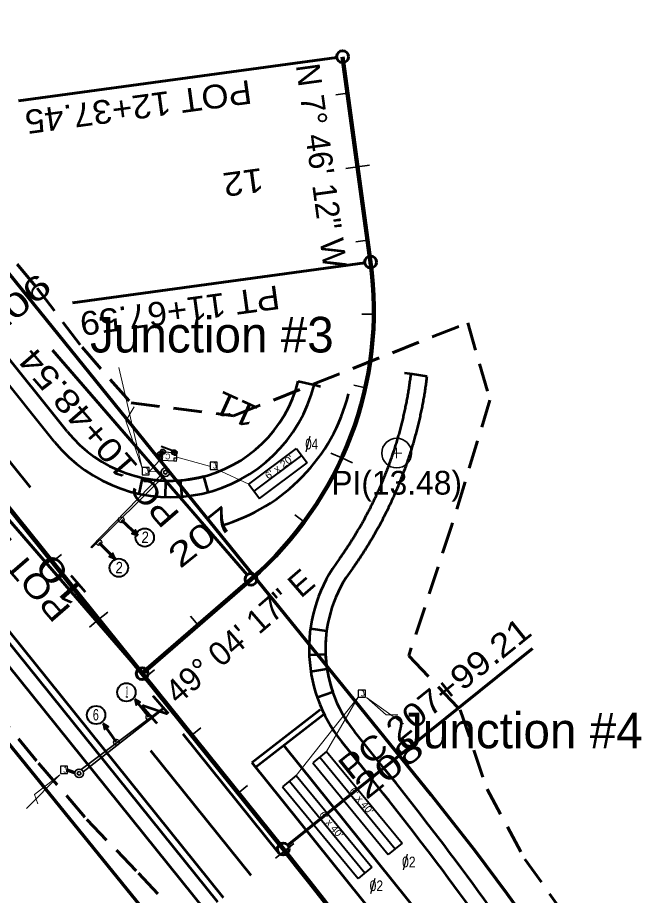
# Model space of a CAD drawing. Extents: x 2717836 to 2719883, y 337327 to 339813.
# Drawn here: x 2718311.5 to 2718519.7, y 339092.2 to 339388.1 of the extents above; entities that cross this region are included whole.
import ezdxf
from ezdxf.enums import TextEntityAlignment as Align

# ---------------------------------------------------------------- set-up
doc = ezdxf.new("R2010")
doc.units = 0
doc.header["$LTSCALE"] = 3.2
doc.header["$PDMODE"] = 32
doc.header["$PDSIZE"] = 1.6
doc.linetypes.add('MEDIUM_DASHED', pattern=[4.5, 3, -1.5])
doc.linetypes.add('SHORT_DASHED', pattern=[2.7, 1.5, -1.2])
for name, color, linetype, lineweight in [('1', 7, 'Continuous', 106), ('17', 7, 'Continuous', 40), ('18', 7, 'Continuous', 35), ('2', 7, 'Continuous', 13), ('22', 7, 'SHORT_DASHED', 60), ('23', 7, 'Continuous', 70), ('28', 7, 'Continuous', 25), ('31', 7, 'Continuous', 35), ('4', 7, 'Continuous', 53), ('50', 7, 'Continuous', 13), ('55', 7, 'Continuous', 13), ('7', 7, 'Continuous', 53)]:
    doc.layers.add(name, color=color, linetype=linetype, lineweight=lineweight)

msp = doc.modelspace()

# ---------------------------------------------------------------- linework, layer by layer
at = {"layer": '1'}
for p, q in [((2717900.042, 339730.601), (2718401.027, 339107.905)), ((2718430.449, 339305.67), (2718421.004, 339374.89)), ((2718353.494, 339166.985), (2718390.165, 339198.783))]:
    msp.add_line(p, q, dxfattribs=at)
for centre, radius, start, end in [((2718311.551, 339289.446), 120, 310.92863, 7.77011), ((2717543.972, 338418.37), 1100, 26.79977, 38.81809)]:
    msp.add_arc(centre, radius, start, end, dxfattribs=at)
at = {"layer": '17'}
for p, q in [((2718365.285, 339241.467), (2718359.882, 339243.563)), ((2718389.458, 339230.856), (2718405.455, 339242.861)), ((2718391.259, 339228.457), (2718407.255, 339240.461)), ((2718405.455, 339242.861), (2718409.056, 339238.061)), ((2718393.059, 339226.057), (2718409.056, 339238.061)), ((2718389.458, 339230.856), (2718393.059, 339226.057)), ((2718415.627, 339140.709), (2718410.994, 339136.896)), ((2718415.627, 339140.709), (2718441.047, 339109.825)), ((2718410.994, 339136.896), (2718436.414, 339106.012)), ((2718413.311, 339138.803), (2718438.731, 339107.919)), ((2718405.421, 339132.685), (2718400.788, 339128.872)), ((2718403.105, 339130.779), (2718428.525, 339099.895)), ((2718405.421, 339132.685), (2718430.841, 339101.801)), ((2718400.788, 339128.872), (2718426.208, 339097.988)), ((2718441.047, 339109.825), (2718436.414, 339106.012)), ((2718430.841, 339101.801), (2718426.208, 339097.988))]:
    msp.add_line(p, q, dxfattribs=at)
at = {"layer": '17', "lineweight": 25}
for p, q in [((2718359.423, 339239.906), (2718359.482, 339240.862)), ((2718360.493, 339241.749), (2718364.327, 339241.523)), ((2718365.17, 339239.551), (2718365.229, 339240.507)), ((2718360.324, 339238.874), (2718364.158, 339238.648))]:
    msp.add_line(p, q, dxfattribs=at)
for points in [[(2718359.478, 339240.846), (2718360.436, 339240.789), (2718360.493, 339241.749), (2718359.534, 339241.805)], [(2718364.271, 339240.564), (2718365.229, 339240.507), (2718365.285, 339241.467), (2718364.327, 339241.523)], [(2718359.365, 339238.93), (2718360.324, 339238.874), (2718360.38, 339239.833), (2718359.422, 339239.889)], [(2718364.155, 339238.648), (2718365.113, 339238.592), (2718365.17, 339239.551), (2718364.211, 339239.607)], [(2718376.391, 339238.235), (2718376.391, 339235.835), (2718378.791, 339235.835), (2718378.791, 339238.235)], [(2718353.506, 339236.405), (2718353.506, 339234.005), (2718355.906, 339234.005), (2718355.906, 339236.405)], [(2718426.282, 339161.454), (2718426.282, 339159.054), (2718428.682, 339159.054), (2718428.682, 339161.454)], [(2718325.972, 339135.761), (2718325.972, 339133.361), (2718328.372, 339133.361), (2718328.372, 339135.761)]]:
    msp.add_lwpolyline(points, close=True, dxfattribs=at)
at = {"layer": '17'}
for p in [(2718359.42, 339239.889), (2718359.478, 339240.846), (2718360.493, 339241.749), (2718364.327, 339241.523)]:
    msp.add_point(p, dxfattribs=at)
at = {"layer": '18'}
for p, q in [((2718336.568, 339209.363), (2718360.775, 339233.522)), ((2718358.969, 339231.639), (2718358.936, 339231.635)), ((2718360.321, 339155.209), (2718332.995, 339134.645)), ((2718335.045, 339136.259), (2718335.078, 339136.258))]:
    msp.add_line(p, q, dxfattribs=at)
at = {"layer": '18', "lineweight": 60}
for p, q in [((2718352.077, 339213.49), (2718346.526, 339218.755)), ((2718344.395, 339205.645), (2718339.02, 339211.091)), ((2718350.989, 339158.435), (2718355.688, 339152.397)), ((2718340.326, 339150.222), (2718344.739, 339143.973))]:
    msp.add_line(p, q, dxfattribs=at)
at = {"layer": '18'}
for points in [[(2718360.099, 339234.174), (2718336.331, 339209.685), (2718336.568, 339209.363)], [(2718333.574, 339133.905), (2718360.512, 339154.857), (2718360.321, 339155.209)]]:
    msp.add_lwpolyline(points, dxfattribs=at)
at = {"layer": '18', "lineweight": 40}
for points in [[(2718352.077, 339213.49), (2718351.247, 339215.459), (2718350.068, 339214.215)], [(2718344.395, 339205.645), (2718343.63, 339207.64), (2718342.41, 339206.436)], [(2718350.989, 339158.435), (2718351.514, 339156.364), (2718352.867, 339157.417)], [(2718340.326, 339150.222), (2718340.755, 339148.13), (2718342.155, 339149.118)]]:
    msp.add_lwpolyline(points, close=True, dxfattribs=at)
at = {"layer": '18'}
for centre, radius in [((2718361.329, 339234.86), 1.448), ((2718361.329, 339234.86), 0.621), ((2718332.26, 339133.396), 1.448), ((2718332.26, 339133.396), 0.621)]:
    msp.add_circle(centre, radius, dxfattribs=at)
at = {"layer": '18', "lineweight": 25}
for centre in [(2718346.453, 339218.821), (2718338.949, 339211.159), (2718355.75, 339152.321), (2718344.799, 339143.894)]:
    msp.add_circle(centre, 0.96, dxfattribs=at)
at = {"layer": '18', "lineweight": 40}
for centre in [(2718354.383, 339212.863), (2718345.636, 339202.653), (2718348.187, 339160.716), (2718337.983, 339153.058)]:
    msp.add_circle(centre, 3.09, dxfattribs=at)
at = {"layer": '2', "lineweight": 53}
for p, q in [((2718390.451, 339137.002), (2718413.427, 339154.882)), ((2718391.68, 339135.423), (2718414.655, 339153.303)), ((2718328.377, 339134.473), (2718330.81, 339133.637))]:
    msp.add_line(p, q, dxfattribs=at)
at = {"layer": '2', "linetype": 'MEDIUM_DASHED', "lineweight": 53}
for p, q in [((2718328.352, 339134.694), (2718330.859, 339133.809)), ((2718328.377, 339134.325), (2718330.884, 339133.464))]:
    msp.add_line(p, q, dxfattribs=at)
at = {"layer": '2'}
for points in [[(2718345.69, 339270.157), (2718353.486, 339236.226), (2718348.029, 339252.217), (2718350.758, 339256.897)], [(2718441.582, 339150.035), (2718429.108, 339159.005), (2718435.735, 339153.155), (2718439.633, 339153.155)], [(2718314.506, 339121.564), (2718325.81, 339132.874), (2718317.235, 339126.244), (2718318.404, 339123.124)]]:
    msp.add_lwpolyline(points, dxfattribs=at)
at = {"layer": '22', "linetype": 'MEDIUM_DASHED'}
for p, q in [((2718302.106, 339316.085), (2718318.127, 339296.888)), ((2718384.304, 339253.87), (2718463.152, 339285.219)), ((2718463.152, 339285.219), (2718470.67, 339259.182)), ((2718349.808, 339258.203), (2718384.304, 339253.87)), ((2718470.67, 339259.182), (2718457.714, 339216.671)), ((2718457.714, 339216.671), (2718443.286, 339172.977)), ((2718443.286, 339172.977), (2718460.664, 339154.801)), ((2718302.767, 339156.183), (2718318.581, 339136.82)), ((2718460.664, 339154.801), (2718469.661, 339128.028)), ((2718318.581, 339136.82), (2718334.858, 339117.828)), ((2718469.661, 339128.028), (2718482.392, 339104.5)), ((2718334.858, 339117.828), (2718352.29, 339099.766)), ((2718352.29, 339099.766), (2718369.341, 339081.436))]:
    msp.add_line(p, q, dxfattribs=at)
for points in [[(2718318.127, 339296.888), (2718333.232, 339276.954), (2718349.808, 339258.203)], [(2718482.392, 339104.5), (2718497.743, 339082.997), (2718512.6, 339061.15)]]:
    msp.add_lwpolyline(points, dxfattribs=at)
at = {"layer": '23'}
for points in [[(2718450.804, 339126.177), (2718423.202, 339160.278), (2718356.64, 339242.515), (2718281.562, 339335.271)], [(2718625.836, 338603.023), (2718449.262, 338959.135), (2718424.429, 339000.578), (2718281.942, 339176.113)]]:
    msp.add_lwpolyline(points, dxfattribs=at)
msp.add_arc((2717727.191, 338544.436), 928.46, 26.92138, 38.79718, dxfattribs=at)
at = {"layer": '28'}
for p, q in [((2718408.758, 339241.752), (2718410.146, 339246.981)), ((2718441.491, 339100.911), (2718442.87, 339106.142)), ((2718430.557, 339092.888), (2718431.936, 339098.119))]:
    msp.add_line(p, q, dxfattribs=at)
at = {"layer": '31', "lineweight": 60}
for p, q in [((2718419.022, 339374.62), (2718311.858, 339359.997)), ((2718428.468, 339305.399), (2718329.979, 339291.96)), ((2718388.855, 339200.294), (2718323.24, 339275.965)), ((2718352.184, 339168.496), (2718281.617, 339249.878)), ((2718402.585, 339109.158), (2718484.989, 339175.456))]:
    msp.add_line(p, q, dxfattribs=at)
at = {"layer": '31'}
for p, q in [((2718422.687, 339362.557), (2718418.724, 339362.016)), ((2718426.067, 339337.786), (2718422.104, 339337.245)), ((2718426.067, 339337.786), (2718430.03, 339338.327)), ((2718429.447, 339313.016), (2718425.484, 339312.475)), ((2718431.544, 339288.134), (2718427.544, 339288.177)), ((2718428.678, 339263.344), (2718424.774, 339264.214)), ((2718420.747, 339239.683), (2718417.107, 339241.342)), ((2718420.747, 339239.683), (2718424.386, 339238.024)), ((2718408.093, 339218.174), (2718404.875, 339220.55)), ((2718323.166, 339204.681), (2718326.282, 339207.189)), ((2718391.264, 339199.748), (2718388.607, 339202.738)), ((2718338.837, 339185.203), (2718341.953, 339187.71)), ((2718338.837, 339185.203), (2718335.72, 339182.696)), ((2718372.382, 339183.363), (2718369.762, 339186.385)), ((2718353.494, 339166.985), (2718350.874, 339170.007)), ((2718353.494, 339166.985), (2718356.114, 339163.963)), ((2718354.508, 339165.724), (2718357.625, 339168.232)), ((2718370.179, 339146.246), (2718373.296, 339148.753)), ((2718385.851, 339126.767), (2718388.967, 339129.275)), ((2718401.522, 339107.289), (2718398.403, 339104.784)), ((2718401.522, 339107.289), (2718404.64, 339109.794))]:
    msp.add_line(p, q, dxfattribs=at)
at = {"layer": '31', "lineweight": 60}
for centre in [(2718421.004, 339374.89), (2718430.449, 339305.67), (2718390.165, 339198.783), (2718353.494, 339166.985), (2718401.027, 339107.905)]:
    msp.add_circle(centre, 2, dxfattribs=at)
at = {"layer": '31'}
msp.add_circle((2718439.229, 339241.326), 5, dxfattribs=at)
at = {"layer": '4'}
for p, q in [((2718323.984, 339245.141), (2718233.831, 339357.196)), ((2718221.365, 339347.167), (2718315.812, 339229.774)), ((2718193.316, 339324.6), (2718380.769, 339091.606)), ((2718444.565, 339267.916), (2718441.886, 339268.255)), ((2718413.545, 339263.674), (2718410.941, 339264.386)), ((2718367.252, 339146.694), (2718399.468, 339106.651)), ((2718401.177, 339142.814), (2718473.847, 339052.489)), ((2718430.634, 339131.725), (2718420.755, 339144.004)), ((2718356.351, 339141.1), (2718390.119, 339099.129)), ((2718390.451, 339137.002), (2718461.947, 339048.136))]:
    msp.add_line(p, q, dxfattribs=at)
for centre, radius, start, end in [((2718362.941, 339276.483), 50, 218.81809, 345.8429), ((2718362.941, 339276.483), 62, 286.08123, 345.8429), ((2718459.709, 339175.349), 50, 142.40011, 218.81809), ((2717543.972, 338418.37), 1138, 33.56822, 38.81809)]:
    msp.add_arc(centre, radius, start, end, dxfattribs=at)
msp.add_spline([(2718420.093, 339205.853), (2718420.618, 339206.601), (2718421.145, 339207.362), (2718421.66, 339208.116), (2718422.176, 339208.883), (2718422.68, 339209.644), (2718423.18, 339210.408), (2718423.68, 339211.185), (2718424.169, 339211.955), (2718424.652, 339212.729), (2718425.136, 339213.515), (2718425.609, 339214.294), (2718426.082, 339215.086), (2718426.544, 339215.871), (2718427, 339216.659), (2718427.458, 339217.46), (2718427.903, 339218.254), (2718428.343, 339219.05), (2718428.784, 339219.859), (2718429.213, 339220.661), (2718429.642, 339221.475), (2718430.06, 339222.282), (2718430.473, 339223.092), (2718430.886, 339223.914), (2718431.287, 339224.729), (2718431.683, 339225.546), (2718432.079, 339226.376), (2718432.463, 339227.198), (2718432.847, 339228.032), (2718433.221, 339228.859), (2718433.589, 339229.687), (2718433.956, 339230.529), (2718434.312, 339231.362), (2718434.663, 339232.197), (2718435.013, 339233.045), (2718435.352, 339233.885), (2718435.69, 339234.737), (2718436.018, 339235.58), (2718436.34, 339236.426), (2718436.661, 339237.284), (2718436.971, 339238.133), (2718437.28, 339238.994), (2718437.579, 339239.847), (2718437.872, 339240.702), (2718438.163, 339241.569), (2718438.445, 339242.427), (2718438.72, 339243.287), (2718438.994, 339244.159), (2718439.258, 339245.022), (2718439.52, 339245.897), (2718439.772, 339246.762), (2718440.018, 339247.63), (2718440.262, 339248.509), (2718440.496, 339249.379), (2718440.725, 339250.25), (2718440.951, 339251.134), (2718441.168, 339252.008), (2718441.382, 339252.894), (2718441.587, 339253.77), (2718441.786, 339254.647), (2718441.981, 339255.536), (2718442.169, 339256.416), (2718442.35, 339257.296), (2718442.527, 339258.188), (2718442.697, 339259.071), (2718442.862, 339259.965), (2718443.02, 339260.849), (2718443.171, 339261.733), (2718443.319, 339262.63), (2718443.458, 339263.516), (2718443.591, 339264.403), (2718443.721, 339265.302), (2718443.842, 339266.19), (2718444.069, 339267.978)], degree=3, dxfattribs=at)
at = {"layer": '50'}
for p, q in [((2718356.003, 339235.25), (2718359.444, 339238.904)), ((2718365.203, 339239.888), (2718376.229, 339236.937)), ((2718355.933, 339235.11), (2718359.866, 339234.969)), ((2718378.791, 339235.835), (2718389.458, 339230.856)), ((2718426.282, 339159.054), (2718405.421, 339132.685)), ((2718426.282, 339159.054), (2718415.627, 339140.709))]:
    msp.add_line(p, q, dxfattribs=at)
at = {"layer": '55'}
for p, q in [((2718439.229, 339243.076), (2718439.229, 339239.576)), ((2718440.979, 339241.326), (2718437.479, 339241.326))]:
    msp.add_line(p, q, dxfattribs=at)
at = {"layer": '7'}
for p, q in [((2718328.27, 339248.589), (2718238.01, 339360.777)), ((2718191.368, 339323.033), (2718378.821, 339090.039)), ((2718187.473, 339319.899), (2718374.925, 339086.905)), ((2718449.498, 339267.099), (2718444.565, 339267.916)), ((2718406.09, 339265.6), (2718410.941, 339264.386)), ((2718352.475, 339227.476), (2718353.569, 339232.867)), ((2718361.317, 339226.49), (2718361.437, 339231.966)), ((2718366.929, 339226.682), (2718366.434, 339232.137)), ((2718375.682, 339228.27), (2718374.223, 339233.573)), ((2718410.162, 339182.179), (2718415.614, 339181.453)), ((2718409.777, 339173.291), (2718415.248, 339173.541)), ((2718410.348, 339167.705), (2718415.756, 339168.567)), ((2718412.525, 339159.079), (2718417.717, 339160.894)), ((2718434.919, 339135.173), (2718425.04, 339147.452))]:
    msp.add_line(p, q, dxfattribs=at)
for centre, radius, start, end in [((2718362.941, 339276.483), 44.5, 218.81809, 345.8429), ((2718362.416, 339276.478), 44.5, 258.5328, 285.38632), ((2718459.709, 339175.349), 44.5, 142.40011, 218.81809), ((2718459.724, 339175.579), 44.5, 172.41557, 199.26909), ((2717543.972, 338418.37), 1143.5, 33.56822, 38.81809)]:
    msp.add_arc(centre, radius, start, end, dxfattribs=at)
msp.add_spline([(2718424.45, 339202.497), (2718424.998, 339203.275), (2718425.547, 339204.065), (2718426.084, 339204.849), (2718426.622, 339205.645), (2718427.148, 339206.436), (2718427.668, 339207.23), (2718428.19, 339208.037), (2718428.7, 339208.838), (2718429.204, 339209.641), (2718429.709, 339210.458), (2718430.201, 339211.268), (2718430.695, 339212.091), (2718431.177, 339212.907), (2718431.653, 339213.726), (2718432.13, 339214.558), (2718432.595, 339215.383), (2718433.054, 339216.211), (2718433.513, 339217.052), (2718433.961, 339217.885), (2718434.409, 339218.732), (2718434.845, 339219.571), (2718435.276, 339220.412), (2718435.706, 339221.267), (2718436.125, 339222.114), (2718436.539, 339222.963), (2718436.952, 339223.826), (2718437.353, 339224.68), (2718437.754, 339225.548), (2718438.144, 339226.407), (2718438.528, 339227.269), (2718438.911, 339228.143), (2718439.284, 339229.01), (2718439.65, 339229.878), (2718440.015, 339230.76), (2718440.37, 339231.633), (2718440.723, 339232.519), (2718441.065, 339233.396), (2718441.402, 339234.275), (2718441.737, 339235.167), (2718442.061, 339236.05), (2718442.384, 339236.946), (2718442.697, 339237.833), (2718443.003, 339238.722), (2718443.308, 339239.624), (2718443.602, 339240.516), (2718443.89, 339241.41), (2718444.177, 339242.317), (2718444.453, 339243.215), (2718444.726, 339244.125), (2718444.99, 339245.025), (2718445.248, 339245.927), (2718445.503, 339246.842), (2718445.749, 339247.747), (2718445.988, 339248.653), (2718446.225, 339249.572), (2718446.452, 339250.481), (2718446.676, 339251.403), (2718446.891, 339252.315), (2718447.099, 339253.227), (2718447.305, 339254.152), (2718447.501, 339255.067), (2718447.691, 339255.983), (2718447.877, 339256.912), (2718448.055, 339257.83), (2718448.229, 339258.76), (2718448.394, 339259.68), (2718448.553, 339260.6), (2718448.708, 339261.533), (2718448.855, 339262.455), (2718448.995, 339263.378), (2718449.131, 339264.313), (2718449.259, 339265.237), (2718449.498, 339267.099)], degree=3, dxfattribs=at)

# ---------------------------------------------------------------- texts
at = {"layer": '17'}
for s, height, rotation, width, p in [('C', 1.919, 176.632, 0.8, (2718362.213, 339241.138)), ("6' x 20'", 2.4, 36.885, 1.1, (2718400.365, 339235.62)), ('J', 1.92, 12.014, 1.15, (2718378.128, 339236.161)), ('J', 1.92, 12.014, 1.15, (2718355.242, 339234.331)), ('J', 1.92, 12.014, 1.15, (2718428.019, 339159.38)), ('J', 1.92, 12.014, 1.15, (2718327.709, 339133.688)), ("6' x 40'", 2.4, 309.457, 1.05, (2718426.467, 339123.366)), ("6' x 40'", 2.4, 309.457, 1.05, (2718416.261, 339115.344))]:
    msp.add_text(s, height=height, rotation=rotation, dxfattribs=dict(at, width=width)).set_placement(p, align=Align.CENTER)
at = {"layer": '18'}
for s, rotation, width, p in [('2', 357.264, 0.85, (2718353.207, 339211.077)), ('2', 357.264, 0.85, (2718344.46, 339200.867)), ('1', 358.176, 0.3, (2718347.764, 339158.959)), ('6', 359.088, 0.7, (2718336.865, 339151.235))]:
    msp.add_text(s, height=3.84, rotation=rotation, dxfattribs=dict(at, width=width)).set_placement(p)
at = {"layer": '2'}
for s, p in [('Junction #3', (2718335.945, 339275.219)), ('Junction #4', (2718440.022, 339141.836))]:
    msp.add_text(s, height=12, dxfattribs=at).set_placement(p)
at = {"layer": '28'}
for s, rotation, width, p in [('04', 359.625, 0.8, (2718410.589, 339242.561)), ('02', 359.718, 0.85, (2718443.319, 339101.722)), ('02', 359.718, 0.85, (2718432.385, 339093.699))]:
    msp.add_text(s, height=3.6, rotation=rotation, dxfattribs=dict(at, width=width)).set_placement(p, align=Align.CENTER)
at = {"layer": '31'}
for s, rotation, p in [('N 7° 46\' 12" W', 277.77, (2718409.947, 339337.576)), ('N 49° 04\' 17" E', 40.929, (2718384.932, 339173.067))]:
    msp.add_text(s, height=8, rotation=rotation, dxfattribs=at).set_placement(p, align=Align.CENTER)
for s, rotation, width, p in [('POT 12+37.45', 187.77, 1.1, (2718389.771, 339367.096)), ('12', 187.77, 1.15, (2718393.82, 339337.423)), ('206', 38.818, 1.45, (2718303.592, 339280.06)), ('PT 11+67.59', 187.77, 1.1, (2718399.216, 339297.875)), ('PC 10+48.54', 130.929, 1.2, (2718366.557, 339220.667)), ('11', 155.5, 1.2, (2718393.287, 339256.593)), ('POT 10+00.00', 130.929, 1.2, (2718329.886, 339188.869)), ('207', 38.818, 1.4, (2718366.277, 339202.146)), ('10', 130.929, 1.6, (2718335.552, 339193.782)), ('PC 207+99.21', 38.818, 1.15, (2718423.765, 339130.691)), ('208', 38.777, 1.45, (2718428.974, 339124.212))]:
    msp.add_text(s, height=8, rotation=rotation, dxfattribs=dict(at, width=width)).set_placement(p)
msp.add_text('PI(13.48)', height=8, dxfattribs=at).set_placement((2718439.229, 339227.326), align=Align.CENTER)

doc.saveas('drawing.dxf')
